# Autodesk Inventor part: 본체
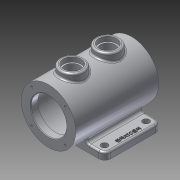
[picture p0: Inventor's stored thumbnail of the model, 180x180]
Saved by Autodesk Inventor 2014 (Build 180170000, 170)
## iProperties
Created: 2014-12
Part Number: 본체
Material: 알루미늄 6061
Document SubType Name: Modeling
Designer: Owner
Density: 2.71 g/cm^3
Appearance: 알루미늄 - 평지
Mass: 1293.15 g
Surface Area: 1041.93 cm^2
Volume: 477.177 cm^3
Author: Owner
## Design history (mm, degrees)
node "작업 평면1"
sketch "스케치3"
  geometry: C1 r 46 at (0, 0); 1 further point
  constraints: 1 centre point, 1 coincident
  dimensions: "d1" = 92 diameter of C1
extrude "돌출1" new body sketch "스케치3" stored distance "d2" = 140; taper "d3" = 0 deg
node "작업 평면2"
node "작업 평면5"
sketch "스케치6"
  geometry: L1 (46, 70)-(-46, 70) reference; L2 (-46, -70)-(46, -70) reference; L3 (-65, 55)-(65, 55); L4 (65, 55)-(65, -40); L5 (65, -40)-(-65, -40); L6 (-65, -40)-(-65, 55); 2 further points
  constraints: 8 end point, 2 parallel, 1 horizontal, 1 midpoint, 1 perpendicular, 1 vertical alignment
  dimensions: "d18" = 130 distance of L3.start L3.end; "d19" = 15 vertical distance of L3.end L1.start; "d20" = 95 distance of L3.end L4.end
extrude "돌출4" join sketch "스케치6" distance "d21" = 12; taper "d22" = 0 deg
node "작업 평면6"
sketch "스케치7"
  geometry: L1 (46, 70)-(-46, 70) reference; L2 (-46, -70)-(46, -70) reference; C1 r 20 at (0, 30); C2 r 20 at (0, -30); 1 further point
  constraints: 2 centre point, 2 vertical alignment
  dimensions: "d24" = 40 diameter of C1; "d25" = 40 diameter of C2; "d26" = 40 distance from line of L1 C1.centre; "d27" = 40 distance from line of L2 C2.centre
extrude "돌출5" join sketch "스케치7" stored distance "d28" = 12; taper "d29" = 0 deg
sketch "스케치8"
  geometry: C1 r 20 at (0, 0) reference; C2 r 20 at (0, -60) reference; C3 r 15 at (0, 0); C4 r 15 at (0, -60); 1 further point
  constraints: 2 centre point, 2 coincident
  dimensions: "d30" = 30 diameter of C3; "d31" = 30 diameter of C4
extrude "돌출6" cut sketch "스케치8" distance "d32" = 8; taper "d33" = 0 deg
sketch "스케치9"
  geometry: C1 r 15 at (0, 0) reference; C2 r 15 at (0, -60) reference; C3 r 12.5 at (0, 0); C4 r 12.5 at (0, -60); 1 further point
  constraints: 2 centre point, 2 coincident
  dimensions: "d34" = 25 diameter of C3; "d35" = 25 diameter of C4
sketch "스케치10"
  geometry: C1 r 46 at (0, 0) reference; C2 r 30 at (0, 0)
  constraints: 1 centre point, 1 coincident
  dimensions: "d36" = 60 diameter of C2
extrude "돌출7" cut sketch "스케치10" distance "d37" = 12; taper "d38" = 0 deg
sketch "스케치11"
  geometry: C1 r 30 at (0, 0) reference; C2 r 37.5 at (0, 0)
  constraints: 1 centre point, 1 coincident
  dimensions: "d39" = 75 diameter of C2
extrude "돌출8" cut sketch "스케치11" distance "d40" = 116; taper "d41" = 0 deg
sketch "스케치12"
  geometry: C1 r 46 at (0, 0) reference; C2 r 30 at (0, 0)
  constraints: 1 centre point, 1 coincident
  dimensions: "d42" = 60 diameter of C2
extrude "돌출9" cut sketch "스케치12" distance "d43" = 12; taper "d44" = 0 deg
extrude "돌출10" cut sketch "스케치9" stored distance "d45" = 12; taper "d46" = 0 deg
sketch "스케치13"
  geometry: L1 (0, 0)-(28.284, 28.284); L2 (0, 0)-(40, 0); C1 r 46 at (0, 0) reference; 1 further point
  constraints: 4 end point, 1 coincident, 1 equal length, 1 horizontal
  dimensions: "d47" = 40 distance of L1.start L1.end; "d48" = 45 deg angle of L2 L1
hole "구멍1" sketch "스케치13" at (28.284, 28.284) diameter "d49" = 3.242; stored, may be unused: countersink angle "d53" = 90 deg, drill point angle "d55" = 118 deg; dims "d50" = 8, "d51" = 4, "d52" = 2, "d54" = 10
sketch "스케치14"
  geometry: L1 (0, 0)-(28.284, 28.284); L2 (0, 0)-(40, 0); C1 r 46 at (0, 0) reference; 1 further point
  constraints: 4 end point, 1 coincident, 1 equal length, 1 horizontal
  dimensions: "d59" = 40 distance of L1.start L1.end; "d60" = 45 deg angle of L2 L1
hole "구멍2" sketch "스케치14" at (28.284, 28.284) diameter "d61" = 3.242; stored, may be unused: countersink angle "d65" = 90 deg, drill point angle "d67" = 118 deg; dims "d62" = 8, "d63" = 4, "d64" = 2, "d66" = 10
sketch "스케치15"
  geometry: L1 (65, -40)-(65, 55) reference; 3 further points
  constraints: 1 horizontal alignment, 1 midpoint, 1 other
  dimensions: "d71" = 8 distance of point (65, 7.5) point (57, 7.5)
feature "엠보싱1" sketch "스케치15" dims "d26" = 40, "d72" = 1, "d73" = 0
sketch "스케치16"
  geometry: L1 (65, -40)-(65, 55) reference; L2 (65, 55)-(25.923, 55) reference; 2 further points
  dimensions: "d74" = 12.5 distance from line of point (52, 42.5) L2; "d75" = 13 distance from line of L1 point (52, 42.5)
hole "구멍3" sketch "스케치16" at (52, 42.5) diameter "d76" = 11; stored, may be unused: countersink angle "d80" = 90 deg, drill point angle "d82" = 0 deg; dims "d77" = 8, "d78" = 4, "d79" = 2, "d81" = 10
fillet "모깎기1" dims "d86" = 10
fillet "모깎기2" dims "d87" = 5
fillet "모깎기3" dims "d88" = 3
chamfer "모따기1" distance "d89" = 1; stored, may be unused: second distance "d90" = 2, angle "d91" = 45 deg
fillet "모깎기4" dims "d92" = 3
fillet "모깎기5" dims "d93" = 3
node "솔리드1"
pattern_circular "원형 패턴1" dims angle "d57" = 360 deg
pattern_circular "원형 패턴2" dims angle "d69" = 360 deg
pattern_linear "직사각형 패턴1" dims "d85" = 70
mirror "대칭1"
node "투영된 루프3"
other parameters: "d0" = 0, "d4" = -106, "d23" = 56
